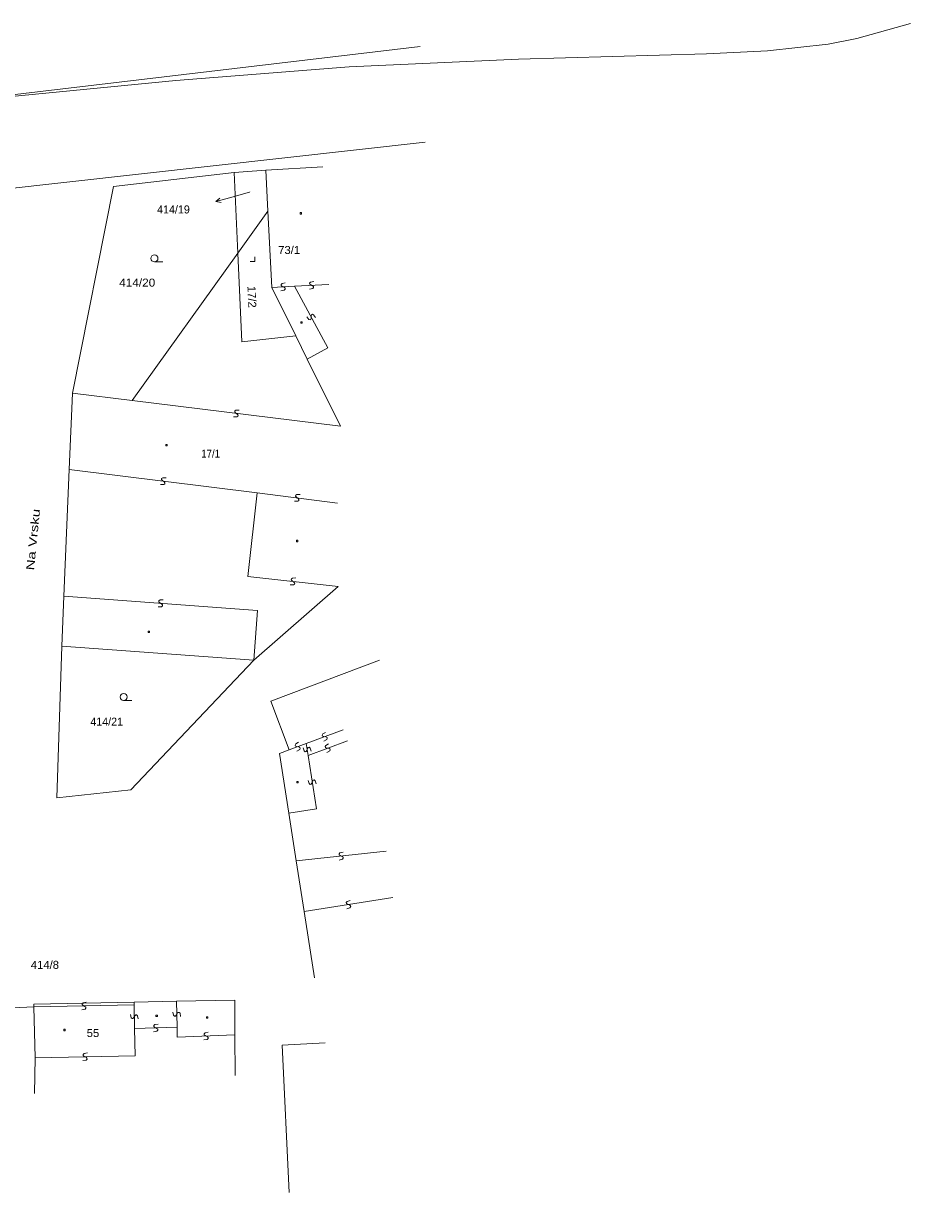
# Model space of a CAD drawing. Extents: x -736847 to -736508, y -1028413 to -1028271.
# Drawn here: x -736602.3 to -736508.1, y -1028400.7 to -1028276.6 of the extents above; entities that cross this region are included whole.
import ezdxf
from ezdxf.enums import TextEntityAlignment as Align

# ---------------------------------------------------------------- set-up
doc = ezdxf.new("R2010")
doc.units = 0
doc.header["$LTSCALE"] = 0.2
doc.layers.add('1', color=7, linetype='Continuous', lineweight=13)
doc.layers.add('2', color=7, linetype='Continuous', lineweight=13)

msp = doc.modelspace()

# ---------------------------------------------------------------- linework, layer by layer
at = {"layer": '1'}
for p, q in [((-736632.81, -1028287.63), (-736560.15, -1028279)), ((-736617.32, -1028295.6), (-736559.64, -1028289.16)), ((-736579.9, -1028292.38), (-736576.56, -1028292.12)), ((-736576.56, -1028292.12), (-736570.49, -1028291.77)), ((-736576.33, -1028296.49), (-736576.56, -1028292.12)), ((-736592.71, -1028293.87), (-736597.07, -1028315.83)), ((-736578.27, -1028294.48), (-736580.4, -1028295.07)), ((-736579.52, -1028300.94), (-736579.1, -1028310.36)), ((-736573.5, -1028304.46), (-736575.92, -1028304.58)), ((-736573.5, -1028304.46), (-736569.86, -1028304.27)), ((-736569.96, -1028311.01), (-736573.5, -1028304.46)), ((-736579.1, -1028310.36), (-736573.37, -1028309.73)), ((-736569.96, -1028311.01), (-736572.14, -1028312.2)), ((-736568.6, -1028319.33), (-736590.74, -1028316.61)), ((-736598.21, -1028342.68), (-736598.73, -1028358.78)), ((-736577.81, -1028344.17), (-736598.21, -1028342.68)), ((-736576.01, -1028348.52), (-736564.47, -1028344.18)), ((-736574.06, -1028353.68), (-736576.01, -1028348.52)), ((-736568.32, -1028351.57), (-736572.26, -1028353.02)), ((-736572.26, -1028353.02), (-736574.06, -1028353.68)), ((-736572.06, -1028354.29), (-736567.89, -1028352.72)), ((-736574.06, -1028353.68), (-736575.09, -1028354.06)), ((-736574.1, -1028360.4), (-736571.18, -1028359.95)), ((-736563.77, -1028364.46), (-736573.32, -1028365.46)), ((-736572.48, -1028370.86), (-736563.05, -1028369.38)), ((-736586.03, -1028380.38), (-736590.54, -1028380.47)), ((-736586.03, -1028380.38), (-736579.83, -1028380.25)), ((-736601.16, -1028380.99), (-736605.21, -1028381.16)), ((-736590.54, -1028380.47), (-736601.17, -1028380.69)), ((-736601.17, -1028380.69), (-736601.16, -1028380.99)), ((-736590.53, -1028380.77), (-736601.16, -1028380.99)), ((-736601.16, -1028380.99), (-736601.05, -1028386.39)), ((-736590.53, -1028380.77), (-736590.54, -1028380.47)), ((-736590.53, -1028380.77), (-736590.48, -1028383.27)), ((-736570.25, -1028384.78), (-736574.82, -1028385.06)), ((-736574.07, -1028400.7), (-736574.82, -1028385.06)), ((-736601.05, -1028386.39), (-736601.11, -1028390.19)), ((-736590.42, -1028386.17), (-736601.05, -1028386.39))]:
    msp.add_line(p, q, dxfattribs=at)
for points in [[(-736847.11, -1028304.1), (-736847.14, -1028305.98), (-736789.15, -1028305.56), (-736765.17, -1028304.89), (-736752.25, -1028304.39), (-736741.06, -1028303.76), (-736733.02, -1028303.04), (-736717.19, -1028301.44), (-736705.39, -1028300.01), (-736699.76, -1028298.26), (-736645.39, -1028290.74), (-736606.84, -1028284.63), (-736586.11, -1028282.62), (-736567.68, -1028281.15), (-736549.73, -1028280.36), (-736529.75, -1028279.79), (-736523.28, -1028279.48), (-736516.84, -1028278.77), (-736513.8, -1028278.17), (-736508.09, -1028276.55)], [(-736592.71, -1028293.87), (-736579.9, -1028292.38), (-736579.52, -1028300.94)], [(-736573.37, -1028309.73), (-736575.92, -1028304.58), (-736576.33, -1028296.49), (-736579.52, -1028300.94)], [(-736579.52, -1028300.94), (-736590.74, -1028316.61), (-736597.07, -1028315.83)], [(-736573.37, -1028309.73), (-736572.14, -1028312.2), (-736568.6, -1028319.33)], [(-736598.21, -1028342.68), (-736597.99, -1028337.38), (-736597.41, -1028323.93), (-736597.07, -1028315.83)], [(-736568.95, -1028327.49), (-736577.46, -1028326.38), (-736597.41, -1028323.93)], [(-736568.87, -1028336.34), (-736578.45, -1028335.28), (-736577.46, -1028326.38)], [(-736598.73, -1028358.78), (-736590.89, -1028357.94), (-736577.81, -1028344.17), (-736568.87, -1028336.34)], [(-736577.81, -1028344.17), (-736577.42, -1028338.88), (-736597.99, -1028337.38)], [(-736572.26, -1028353.02), (-736572.06, -1028354.29), (-736571.18, -1028359.95)], [(-736575.09, -1028354.06), (-736574.1, -1028360.4), (-736573.32, -1028365.46)], [(-736573.32, -1028365.46), (-736572.48, -1028370.86), (-736571.38, -1028377.9)], [(-736579.82, -1028383.96), (-736585.95, -1028384.2), (-736585.97, -1028383.15), (-736586.03, -1028380.38)], [(-736579.83, -1028380.25), (-736579.82, -1028383.96), (-736579.8, -1028388.27)], [(-736585.97, -1028383.15), (-736590.48, -1028383.27), (-736590.42, -1028386.17)]]:
    msp.add_lwpolyline(points, dxfattribs=at)
at = {"layer": '2'}
for p, q in [((-736581.844, -1028295.472), (-736581.43, -1028295.097)), ((-736588.37, -1028301.88), (-736587.495, -1028301.88)), ((-736577.71, -1028301.83), (-736578.21, -1028301.83)), ((-736577.71, -1028301.83), (-736577.71, -1028301.33)), ((-736591.64, -1028348.45), (-736590.765, -1028348.45))]:
    msp.add_line(p, q, dxfattribs=at)
for points in [[(-736580.4, -1028295.07), (-736581.844, -1028295.472), (-736581.296, -1028295.579)], [(-736574.48, -1028304.108), (-736574.827, -1028304.175), (-736574.922, -1028304.28), (-736574.917, -1028304.38), (-736574.812, -1028304.475), (-736574.607, -1028304.564), (-736574.502, -1028304.659), (-736574.497, -1028304.759), (-736574.592, -1028304.864), (-736574.939, -1028304.931)], [(-736571.451, -1028303.952), (-736571.798, -1028304.02), (-736571.892, -1028304.125), (-736571.887, -1028304.225), (-736571.782, -1028304.32), (-736571.577, -1028304.409), (-736571.472, -1028304.504), (-736571.467, -1028304.604), (-736571.561, -1028304.709), (-736571.908, -1028304.777)], [(-736571.259, -1028307.764), (-736571.469, -1028307.48), (-736571.605, -1028307.44), (-736571.693, -1028307.487), (-736571.733, -1028307.623), (-736571.726, -1028307.846), (-736571.766, -1028307.982), (-736571.854, -1028308.029), (-736571.99, -1028307.989), (-736572.2, -1028307.705)], [(-736579.373, -1028317.603), (-736579.726, -1028317.61), (-736579.838, -1028317.697), (-736579.85, -1028317.796), (-736579.763, -1028317.908), (-736579.576, -1028318.031), (-736579.489, -1028318.143), (-736579.501, -1028318.242), (-736579.613, -1028318.329), (-736579.966, -1028318.336)], [(-736587.138, -1028324.788), (-736587.491, -1028324.795), (-736587.603, -1028324.882), (-736587.615, -1028324.981), (-736587.528, -1028325.093), (-736587.341, -1028325.216), (-736587.254, -1028325.328), (-736587.266, -1028325.427), (-736587.378, -1028325.514), (-736587.731, -1028325.521)], [(-736572.905, -1028326.57), (-736573.258, -1028326.575), (-736573.37, -1028326.661), (-736573.383, -1028326.76), (-736573.297, -1028326.872), (-736573.112, -1028326.997), (-736573.026, -1028327.109), (-736573.039, -1028327.208), (-736573.151, -1028327.295), (-736573.504, -1028327.299)], [(-736573.367, -1028335.439), (-736573.72, -1028335.451), (-736573.831, -1028335.539), (-736573.842, -1028335.638), (-736573.753, -1028335.749), (-736573.566, -1028335.87), (-736573.477, -1028335.981), (-736573.488, -1028336.08), (-736573.599, -1028336.168), (-736573.952, -1028336.18)], [(-736587.426, -1028337.749), (-736587.779, -1028337.773), (-736587.886, -1028337.866), (-736587.893, -1028337.965), (-736587.801, -1028338.072), (-736587.608, -1028338.187), (-736587.516, -1028338.294), (-736587.523, -1028338.393), (-736587.63, -1028338.486), (-736587.983, -1028338.51)], [(-736573.062, -1028352.888), (-736573.374, -1028353.055), (-736573.433, -1028353.184), (-736573.399, -1028353.278), (-736573.271, -1028353.337), (-736573.048, -1028353.362), (-736572.92, -1028353.421), (-736572.886, -1028353.515), (-736572.945, -1028353.644), (-736573.257, -1028353.811)], [(-736570.193, -1028351.833), (-736570.504, -1028352.001), (-736570.564, -1028352.129), (-736570.529, -1028352.223), (-736570.401, -1028352.282), (-736570.178, -1028352.307), (-736570.05, -1028352.366), (-736570.015, -1028352.46), (-736570.075, -1028352.588), (-736570.386, -1028352.756)], [(-736569.881, -1028353.042), (-736570.191, -1028353.212), (-736570.25, -1028353.341), (-736570.215, -1028353.435), (-736570.086, -1028353.493), (-736569.863, -1028353.516), (-736569.734, -1028353.574), (-736569.699, -1028353.668), (-736569.758, -1028353.797), (-736570.068, -1028353.967)], [(-736571.725, -1028353.839), (-736571.829, -1028353.501), (-736571.944, -1028353.418), (-736572.042, -1028353.434), (-736572.126, -1028353.548), (-736572.193, -1028353.761), (-736572.277, -1028353.875), (-736572.375, -1028353.891), (-736572.49, -1028353.808), (-736572.594, -1028353.47)], [(-736571.186, -1028357.305), (-736571.289, -1028356.967), (-736571.403, -1028356.883), (-736571.502, -1028356.899), (-736571.585, -1028357.013), (-736571.654, -1028357.226), (-736571.737, -1028357.34), (-736571.836, -1028357.356), (-736571.95, -1028357.272), (-736572.053, -1028356.934)], [(-736568.338, -1028364.536), (-736568.68, -1028364.622), (-736568.769, -1028364.732), (-736568.759, -1028364.831), (-736568.649, -1028364.92), (-736568.44, -1028364.999), (-736568.33, -1028365.088), (-736568.32, -1028365.187), (-736568.409, -1028365.297), (-736568.751, -1028365.383)], [(-736567.58, -1028369.686), (-736567.918, -1028369.789), (-736568.001, -1028369.904), (-736567.985, -1028370.002), (-736567.871, -1028370.086), (-736567.658, -1028370.153), (-736567.544, -1028370.237), (-736567.528, -1028370.335), (-736567.611, -1028370.45), (-736567.949, -1028370.553)], [(-736595.603, -1028380.474), (-736595.952, -1028380.532), (-736596.05, -1028380.634), (-736596.048, -1028380.734), (-736595.946, -1028380.832), (-736595.743, -1028380.927), (-736595.641, -1028381.025), (-736595.639, -1028381.125), (-736595.737, -1028381.227), (-736596.086, -1028381.285)], [(-736585.594, -1028382.006), (-736585.652, -1028381.657), (-736585.754, -1028381.559), (-736585.854, -1028381.561), (-736585.952, -1028381.663), (-736586.047, -1028381.866), (-736586.145, -1028381.968), (-736586.245, -1028381.97), (-736586.347, -1028381.872), (-736586.405, -1028381.523)], [(-736590.1, -1028382.261), (-736590.157, -1028381.913), (-736590.259, -1028381.815), (-736590.359, -1028381.817), (-736590.457, -1028381.919), (-736590.553, -1028382.12), (-736590.65, -1028382.222), (-736590.75, -1028382.224), (-736590.852, -1028382.126), (-736590.909, -1028381.778)], [(-736587.985, -1028382.803), (-736588.334, -1028382.862), (-736588.431, -1028382.965), (-736588.428, -1028383.065), (-736588.326, -1028383.162), (-736588.123, -1028383.257), (-736588.021, -1028383.354), (-736588.018, -1028383.454), (-736588.115, -1028383.557), (-736588.464, -1028383.616)], [(-736582.65, -1028383.67), (-736582.998, -1028383.734), (-736583.094, -1028383.838), (-736583.09, -1028383.937), (-736582.986, -1028384.033), (-736582.783, -1028384.126), (-736582.679, -1028384.222), (-736582.675, -1028384.321), (-736582.771, -1028384.425), (-736583.119, -1028384.489)], [(-736595.493, -1028385.874), (-736595.842, -1028385.932), (-736595.94, -1028386.034), (-736595.938, -1028386.134), (-736595.836, -1028386.232), (-736595.633, -1028386.327), (-736595.531, -1028386.425), (-736595.529, -1028386.525), (-736595.627, -1028386.627), (-736595.976, -1028386.685)]]:
    msp.add_lwpolyline(points, dxfattribs=at)
for points in [[(-736572.9, -1028296.64), (-736572.75, -1028296.64), (-736572.75, -1028296.79), (-736572.9, -1028296.79)], [(-736572.84, -1028308.24), (-736572.69, -1028308.24), (-736572.69, -1028308.39), (-736572.84, -1028308.39)], [(-736587.16, -1028321.25), (-736587.01, -1028321.25), (-736587.01, -1028321.4), (-736587.16, -1028321.4)], [(-736573.29, -1028331.44), (-736573.14, -1028331.44), (-736573.14, -1028331.59), (-736573.29, -1028331.59)], [(-736589.05, -1028341.08), (-736588.9, -1028341.08), (-736588.9, -1028341.23), (-736589.05, -1028341.23)], [(-736573.25, -1028357.04), (-736573.1, -1028357.04), (-736573.1, -1028357.19), (-736573.25, -1028357.19)], [(-736588.21, -1028381.86), (-736588.06, -1028381.86), (-736588.06, -1028382.01), (-736588.21, -1028382.01)], [(-736582.86, -1028382.03), (-736582.71, -1028382.03), (-736582.71, -1028382.18), (-736582.86, -1028382.18)], [(-736597.99, -1028383.36), (-736597.84, -1028383.36), (-736597.84, -1028383.51), (-736597.99, -1028383.51)]]:
    msp.add_lwpolyline(points, close=True, dxfattribs=at)
for centre in [(-736588.37, -1028301.505), (-736591.64, -1028348.075)]:
    msp.add_circle(centre, 0.375, dxfattribs=at)

# ---------------------------------------------------------------- texts
for s, height, p in [('414/19', 0.05, (-736578.27, -1028294.48)), ('414/21', 0.85, (-736595.18, -1028351.12))]:
    msp.add_text(s, height=height, dxfattribs=at).set_placement(p)
msp.add_text('414/19', height=0.85, dxfattribs=at).set_placement((-736584.612, -1028296.73), align=Align.RIGHT)
for s, width, p in [('73/1', 1.05, (-736575.23, -1028301.04)), ('414/20', 1.1, (-736592.11, -1028304.5)), ('17/1', 0.9, (-736583.4, -1028322.66)), ('414/8', 1.05, (-736601.49, -1028376.94)), ('55', 1.05, (-736595.56, -1028384.18))]:
    msp.add_text(s, height=0.85, dxfattribs=dict(at, width=width)).set_placement(p)
at = {"layer": '2', "width": 1.05}
msp.add_text('17/2', height=0.85, rotation=272.553, dxfattribs=at).set_placement((-736578.5, -1028304.44))
at = {"layer": '2', "width": 1.4}
msp.add_text('Na Vrsku', height=0.85, rotation=84.295, dxfattribs=at).set_placement((-736600.833, -1028331.396), align=Align.CENTER)

doc.saveas('drawing.dxf')
